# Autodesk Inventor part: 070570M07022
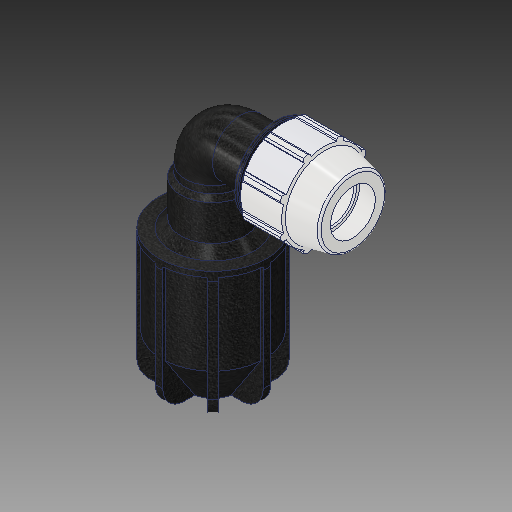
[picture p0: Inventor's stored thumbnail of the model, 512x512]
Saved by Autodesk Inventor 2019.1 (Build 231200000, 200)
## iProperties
Created: 2017-02
Part Number: 070570M07022
Material: PVC-Piping
Description: PLASSON PLASS4 90° ELBOW 3/4'' - 0.73
Document SubType Name: Modeling
Designer: KIM
Mass: 92.6774 g
Surface Area: 199.44 cm^2
Volume: 66.1981 cm^3
Density: 1.4 g/cm^3
Appearance: PTFE
Author: KIM
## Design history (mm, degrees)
derived "070570M0.ipt"
feature "Solid1::070570M0.ipt"
tag "TaggingFeature1"
body "Solid1"
other parameters: "d_" = 26.6, "E_" = 54.102, "A_" = 83.058, "l_" = 59.944, "d_1" = 18.542, "E_1" = 64.008, "l_1" = 104.902, "A_1" = 128.016, "d106" = 32.9921, "d2" = 26.6, "d4" = 11.86543, "d5" = 16.6116, "d7" = 54.102, "d8" = 32.9921, "d9" = 11.86543, "d11" = 2.37309, "d12" = 43.2816, "d13" = 120 deg, "d14" = 39.9, "d15" = 12 deg, "d16" = 48.6918, "d18" = 1.33, "d19" = 35 deg, "d20" = 17.5 deg, "d21" = 50.31486, "d23" = 0, "d25" = 360 deg, "d27" = 1.08204, "d42" = 24.9174, "d43" = 1.62306, "d46" = 0.798, "d53" = 0.532, "d67" = 2.7051, "d70" = 23.94, "d71" = 59.944, "d73" = 83.058, "d74" = 90 deg, "d75" = 18.542, "d76" = 64.008, "d77" = 128.016, "d78" = 0.83058, "d80" = 23.94, "d82" = 104.902, "d84" = 60.8076, "d85" = 135 deg, "d86" = 3.2004, "d88" = 104.902, "d89" = 3.2004, "d90" = 135 deg, "d91" = 78.6765, "d92" = 20.48256, "d93" = 26.2255, "d94" = 3.2004, "d95" = 5.2451, "d97" = 4.32816, "d98" = 0, "d100" = 360 deg, "d102" = 70.4088, "d103" = 12.8016, "d104" = 5.12064, "d105" = 0, "d107" = 16.2306, "d108" = 0, "d109" = 0, "d110" = 2.37309
